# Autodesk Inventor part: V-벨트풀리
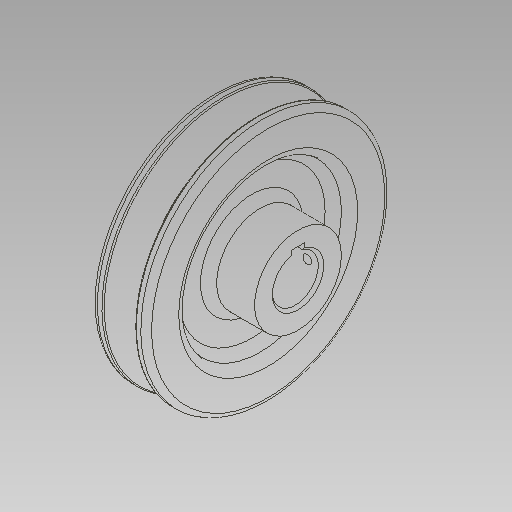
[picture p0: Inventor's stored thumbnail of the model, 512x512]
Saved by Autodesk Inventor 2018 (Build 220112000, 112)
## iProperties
Created: 2015-09
Part Number: V-벨트풀리
Material: 강철, 연강
Document SubType Name: Modeling
Designer: mduedu
Density: 7.86 g/cm^3
Mass: 779.014 g
Surface Area: 277.465 cm^2
Volume: 99.1112 cm^3
Appearance: 강철
Author: mduedu
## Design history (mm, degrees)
sketch "스케치1"
  geometry: L1 (-10, 0)-(10, 0); L2 (-10, 0)-(-10, 45); L3 (-10, 45)-(-5.976, 45); L4 (-5.976, 45)-(-2.154, 32.5); L5 (-2.154, 32.5)-(2.154, 32.5); L6 (2.154, 32.5)-(5.976, 45); L7 (5.976, 45)-(10, 45); L8 (10, 45)-(10, 0); L9 (0, 0)-(0, 32.5); L10 (-10, 40.5)-(10, 40.5); 3 further points
  constraints: 20 end point, 6 point on line, 3 perpendicular, 2 midpoint, 2 parallel, 2 symmetric about line, 1 coincident, 1 collinear, 1 equal length, 1 horizontal, 1 vertical, 1 vertical alignment
  dimensions: "d0" = 20 distance between parallel lines of L8 L2; "d2" = 90 diameter of L3 L1; "d5" = 8 distance between parallel lines of L5 L10; "d6" = 9.2 distance of point (4.6, 40.5) point (-4.6, 40.5); "d7" = 34 deg angle of L6 L4; "d40" = 4.5 distance between parallel lines of L3 L10
revolve "회전1" sketch "스케치1" stored, may be unused: angle "d8" = 90 deg
sketch "스케치2"
  geometry: C1 r 16 at (0, 0); 1 further point
  constraints: 1 centre point, 1 coincident
  dimensions: "d9" = 32 diameter of C1
extrude "돌출1" join sketch "스케치2" distance "d10" = 11; taper "d11" = 0 deg
fillet "모깎기1" dims "d12" = 1, "d13" = 0.5, "d14" = 2
sketch "스케치3"
  geometry: C1 r 16 at (0, 0) reference; C2 r 30 at (0, 0); 1 further point
  constraints: 1 centre point, 1 coincident
  dimensions: "d15" = 60 diameter of C2
extrude "돌출2" cut sketch "스케치3" distance "d16" = 6; taper "d17" = 0 deg
fillet "모깎기2" dims "d18" = 3
fillet "모깎기3" dims "d19" = 3
fillet "모깎기4" dims "d20" = 3
sketch "스케치4"
  geometry: C1 r 8.5 at (0, 0); 1 further point
  constraints: 1 centre point, 1 coincident
  dimensions: "d21" = 17 diameter of C1
extrude "돌출3" cut sketch "스케치4" extent not by distance; stored distance "d22" = 4; taper "d23" = 0 deg
sketch "스케치5"
  geometry: L1 (-2.5, 8.124)-(2.5, 8.124); L2 (2.5, 8.124)-(2.5, 10.8); L3 (2.5, 10.8)-(-2.5, 10.8); L4 (-2.5, 10.8)-(-2.5, 8.124); A1 r 8.5 centre (0, 0) between (-2.5, 8.124) and (2.5, 8.124) reference; 2 further points
  constraints: 8 end point, 3 point on circle, 2 parallel, 1 horizontal, 1 perpendicular, 1 vertical alignment
  dimensions: "d24" = 5 distance of L2.end L3.end; "d26" = 19.3 distance from line of L3 point (0, -8.5)
extrude "돌출4" cut sketch "스케치5" extent not by distance; stored distance "d27" = 4; taper "d28" = 0 deg
chamfer "모따기1" distance "d29" = 1; stored, may be unused: second distance "d30" = 2, angle "d31" = 45 deg
node "작업 평면1"
sketch "스케치6"
  geometry: L1 (-11, 16)-(-11, -16) reference; 2 further points
  constraints: 1 horizontal alignment
  dimensions: "d32" = 5 distance from line of point (-6, 0) L1
hole "구멍1" sketch "스케치6" at (-6, 0) diameter "d33" = 3.242; stored, may be unused: countersink angle "d37" = 90 deg, drill point angle "d39" = 118 deg; dims "d34" = 6, "d35" = 4, "d36" = 2, "d38" = 8
node "솔리드1"
mirror "대칭1"
